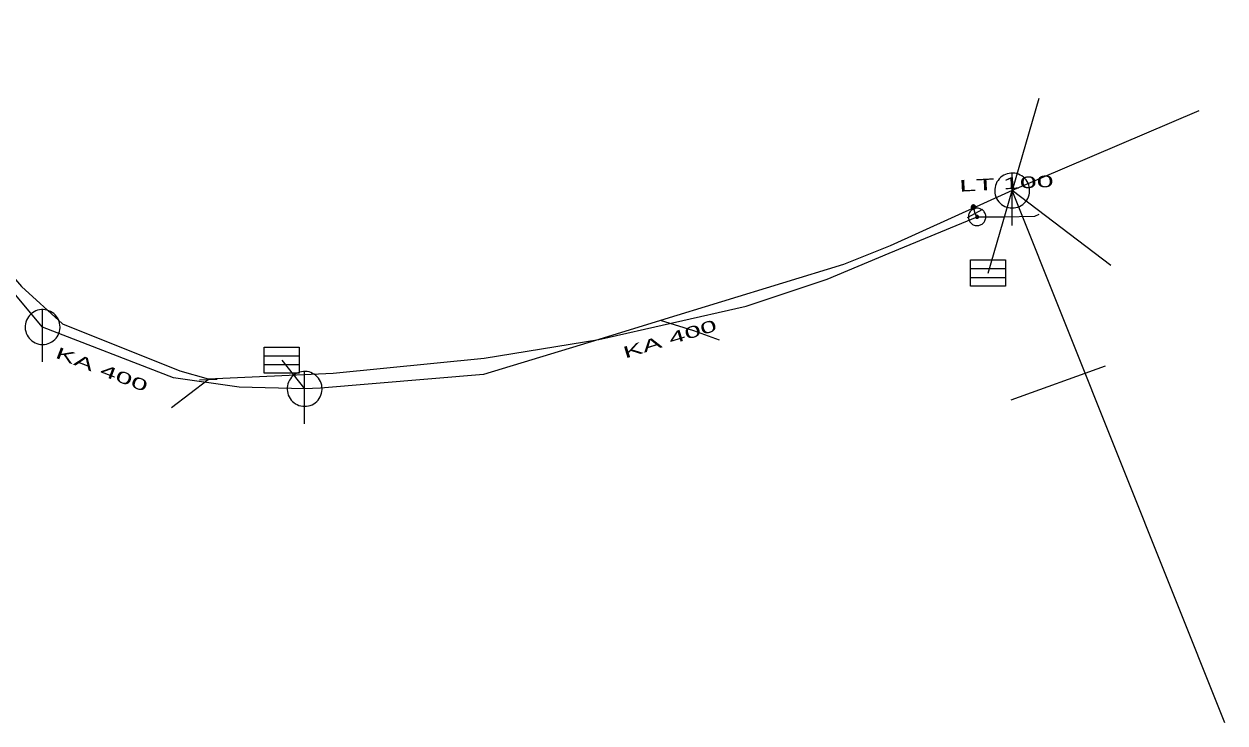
# Model space of a CAD drawing. Extents: x -688432 to -687974, y -973332 to -972704.
# Drawn here: x -688043 to -687974.2, y -972998.2 to -972958.2 of the extents above; entities that cross this region are included whole.
import ezdxf
from ezdxf.enums import TextEntityAlignment as Align

# ---------------------------------------------------------------- set-up
doc = ezdxf.new("R2010")
doc.units = 0
doc.header["$LTSCALE"] = 0.27
for name, color, linetype, lineweight in [('1', 7, 'Continuous', 25), ('11', 7, 'Continuous', 13), ('13', 7, 'Continuous', 13), ('14', 7, 'Continuous', 25), ('17', 7, 'Continuous', 25), ('22', 7, 'Continuous', 13), ('34', 7, 'Continuous', 13), ('47', 7, 'Continuous', 13), ('9', 7, 'Continuous', 13)]:
    doc.layers.add(name, color=color, linetype=linetype, lineweight=lineweight)

msp = doc.modelspace()

# ---------------------------------------------------------------- linework, layer by layer
at = {"layer": '11'}
for p, q in [((-687984.829, -972962.445), (-687986.359, -972967.719)), ((-687987.73, -972972.449), (-687986.359, -972967.719)), ((-687980.71, -972972.02), (-687986.359, -972967.719)), ((-688028.199, -972977.44), (-688026.89, -972979.079))]:
    msp.add_line(p, q, dxfattribs=at)
msp.add_lwpolyline([(-688003.12, -972976.289), (-688004.59, -972975.75), (-688006.5, -972975.16)], dxfattribs=at)
at = {"layer": '13'}
for p, q in [((-687981.03, -972977.77), (-687986.43, -972979.719)), ((-688032.407, -972978.563), (-688034.52, -972980.17))]:
    msp.add_line(p, q, dxfattribs=at)
at = {"layer": '14'}
for p in [(-687975.67, -972963.16), (-687974.17, -972998.219)]:
    msp.add_line(p, (-687986.359, -972967.719), dxfattribs=at)
at = {"layer": '14', "lineweight": 13}
for p, q in [((-687988.48, -972969.03), (-687988.579, -972968.67)), ((-687988.37, -972969.23), (-687988.48, -972969.03)), ((-688032.41, -972978.5), (-688032.407, -972978.563))]:
    msp.add_line(p, q, dxfattribs=at)
at = {"layer": '14'}
for points in [[(-688041.899, -972975.539), (-688045.67, -972971.059), (-688050.98, -972964.93), (-688055.91, -972959.239), (-688056.879, -972958.18)], [(-687986.359, -972967.719), (-687993.34, -972970.89), (-687996.03, -972971.96), (-688006.5, -972975.16), (-688010.039, -972976.26), (-688016.64, -972978.25), (-688025.98, -972979.039), (-688026.89, -972979.079)], [(-688026.89, -972979.079), (-688030.64, -972978.989), (-688034.41, -972978.44), (-688041.899, -972975.539)]]:
    msp.add_lwpolyline(points, dxfattribs=at)
at = {"layer": '17'}
for points in [[(-688050.016, -972965.189), (-688043.1, -972973.21), (-688040.76, -972975.36), (-688034.039, -972978.039), (-688032.41, -972978.5), (-688025.25, -972978.18), (-688016.6, -972977.329), (-688010.039, -972976.26), (-688001.6, -972974.35), (-687996.96, -972972.8), (-687993.41, -972971.309), (-687988.37, -972969.23)], [(-687988.37, -972969.23), (-687986.829, -972969.23), (-687985.07, -972969.188), (-687984.82, -972969.07)]]:
    msp.add_lwpolyline(points, dxfattribs=at)
at = {"layer": '22'}
for p, q in [((-687986.359, -972969.719), (-687986.358, -972966.719)), ((-687988.741, -972972.192), (-687986.741, -972972.192)), ((-687988.741, -972972.692), (-687986.741, -972972.692)), ((-688041.899, -972977.539), (-688041.898, -972974.539)), ((-688029.21, -972977.183), (-688027.21, -972977.183)), ((-688029.21, -972977.683), (-688027.21, -972977.683)), ((-688026.89, -972981.079), (-688026.889, -972978.079))]:
    msp.add_line(p, q, dxfattribs=at)
for points in [[(-687985.359, -972967.719), (-687985.364, -972967.61), (-687985.382, -972967.502), (-687985.412, -972967.396), (-687985.452, -972967.295), (-687985.504, -972967.198), (-687985.566, -972967.108), (-687985.638, -972967.025), (-687985.718, -972966.951), (-687985.806, -972966.885), (-687985.9, -972966.83), (-687986, -972966.785), (-687986.105, -972966.752), (-687986.212, -972966.73), (-687986.321, -972966.72), (-687986.431, -972966.722), (-687986.539, -972966.736), (-687986.646, -972966.761), (-687986.749, -972966.798), (-687986.847, -972966.847), (-687986.939, -972966.905), (-687987.025, -972966.974), (-687987.102, -972967.051), (-687987.171, -972967.137), (-687987.23, -972967.229), (-687987.278, -972967.327), (-687987.315, -972967.43), (-687987.341, -972967.537), (-687987.355, -972967.645), (-687987.358, -972967.755), (-687987.348, -972967.864), (-687987.327, -972967.971), (-687987.293, -972968.075), (-687987.249, -972968.175), (-687987.194, -972968.27), (-687987.128, -972968.358), (-687987.054, -972968.438), (-687986.971, -972968.51), (-687986.881, -972968.572), (-687986.785, -972968.624), (-687986.683, -972968.665), (-687986.578, -972968.695), (-687986.47, -972968.713), (-687986.36, -972968.719), (-687986.251, -972968.713), (-687986.143, -972968.695), (-687986.038, -972968.666), (-687985.936, -972968.625), (-687985.839, -972968.573), (-687985.749, -972968.511), (-687985.666, -972968.44), (-687985.591, -972968.36), (-687985.526, -972968.272), (-687985.47, -972968.178), (-687985.426, -972968.078), (-687985.392, -972967.974), (-687985.37, -972967.866), (-687985.36, -972967.757)], [(-687988.741, -972971.692), (-687986.741, -972971.692), (-687986.741, -972973.192), (-687988.741, -972973.192)], [(-688040.899, -972975.539), (-688040.904, -972975.43), (-688040.922, -972975.322), (-688040.952, -972975.216), (-688040.992, -972975.115), (-688041.044, -972975.018), (-688041.106, -972974.928), (-688041.178, -972974.845), (-688041.258, -972974.771), (-688041.346, -972974.705), (-688041.44, -972974.65), (-688041.54, -972974.605), (-688041.645, -972974.572), (-688041.752, -972974.55), (-688041.861, -972974.54), (-688041.971, -972974.542), (-688042.079, -972974.556), (-688042.186, -972974.581), (-688042.289, -972974.618), (-688042.387, -972974.667), (-688042.479, -972974.725), (-688042.565, -972974.794), (-688042.642, -972974.871), (-688042.711, -972974.957), (-688042.77, -972975.049), (-688042.818, -972975.147), (-688042.855, -972975.25), (-688042.881, -972975.357), (-688042.895, -972975.465), (-688042.898, -972975.575), (-688042.888, -972975.684), (-688042.867, -972975.791), (-688042.833, -972975.895), (-688042.789, -972975.995), (-688042.734, -972976.09), (-688042.668, -972976.178), (-688042.594, -972976.258), (-688042.511, -972976.33), (-688042.421, -972976.392), (-688042.325, -972976.444), (-688042.223, -972976.485), (-688042.118, -972976.515), (-688042.01, -972976.533), (-688041.9, -972976.539), (-688041.791, -972976.533), (-688041.683, -972976.515), (-688041.578, -972976.486), (-688041.476, -972976.445), (-688041.379, -972976.393), (-688041.289, -972976.331), (-688041.206, -972976.26), (-688041.131, -972976.18), (-688041.066, -972976.092), (-688041.01, -972975.998), (-688040.966, -972975.898), (-688040.932, -972975.794), (-688040.91, -972975.686), (-688040.9, -972975.577)], [(-688029.21, -972976.683), (-688027.21, -972976.683), (-688027.21, -972978.183), (-688029.21, -972978.183)], [(-688025.89, -972979.079), (-688025.895, -972978.97), (-688025.913, -972978.862), (-688025.943, -972978.756), (-688025.983, -972978.655), (-688026.035, -972978.558), (-688026.097, -972978.468), (-688026.169, -972978.385), (-688026.249, -972978.311), (-688026.337, -972978.245), (-688026.431, -972978.19), (-688026.531, -972978.145), (-688026.636, -972978.112), (-688026.743, -972978.09), (-688026.852, -972978.08), (-688026.962, -972978.082), (-688027.07, -972978.096), (-688027.177, -972978.121), (-688027.28, -972978.158), (-688027.378, -972978.207), (-688027.47, -972978.265), (-688027.556, -972978.334), (-688027.633, -972978.411), (-688027.702, -972978.497), (-688027.761, -972978.589), (-688027.809, -972978.687), (-688027.846, -972978.79), (-688027.872, -972978.897), (-688027.886, -972979.005), (-688027.889, -972979.115), (-688027.879, -972979.224), (-688027.858, -972979.331), (-688027.824, -972979.435), (-688027.78, -972979.535), (-688027.725, -972979.63), (-688027.659, -972979.718), (-688027.585, -972979.798), (-688027.502, -972979.87), (-688027.412, -972979.932), (-688027.316, -972979.984), (-688027.214, -972980.025), (-688027.109, -972980.055), (-688027.001, -972980.073), (-688026.891, -972980.079), (-688026.782, -972980.073), (-688026.674, -972980.055), (-688026.569, -972980.026), (-688026.467, -972979.985), (-688026.37, -972979.933), (-688026.28, -972979.871), (-688026.197, -972979.8), (-688026.122, -972979.72), (-688026.057, -972979.632), (-688026.001, -972979.538), (-688025.957, -972979.438), (-688025.923, -972979.334), (-688025.901, -972979.226), (-688025.891, -972979.117)]]:
    msp.add_lwpolyline(points, close=True, dxfattribs=at)
at = {"layer": '34'}
for p, q in [((-687988.917, -972969.271), (-687988.041, -972968.789)), ((-688031.907, -972978.54), (-688032.906, -972978.584))]:
    msp.add_line(p, q, dxfattribs=at)
at = {"layer": '47'}
for points in [[(-687987.907, -972969.039), (-687987.93, -972968.992), (-687987.957, -972968.947), (-687987.989, -972968.906), (-687988.025, -972968.868), (-687988.065, -972968.833), (-687988.108, -972968.804), (-687988.154, -972968.779), (-687988.202, -972968.759), (-687988.252, -972968.744), (-687988.304, -972968.734), (-687988.356, -972968.73), (-687988.408, -972968.732), (-687988.46, -972968.738), (-687988.511, -972968.75), (-687988.56, -972968.767), (-687988.607, -972968.79), (-687988.652, -972968.817), (-687988.694, -972968.85), (-687988.731, -972968.885), (-687988.766, -972968.925), (-687988.795, -972968.968), (-687988.821, -972969.014), (-687988.841, -972969.063), (-687988.856, -972969.112), (-687988.865, -972969.164), (-687988.869, -972969.216), (-687988.868, -972969.269), (-687988.861, -972969.32), (-687988.849, -972969.371), (-687988.832, -972969.42), (-687988.809, -972969.467), (-687988.782, -972969.512), (-687988.75, -972969.554), (-687988.714, -972969.591), (-687988.674, -972969.626), (-687988.632, -972969.656), (-687988.586, -972969.681), (-687988.537, -972969.701), (-687988.487, -972969.716), (-687988.435, -972969.725), (-687988.383, -972969.729), (-687988.331, -972969.729), (-687988.279, -972969.721), (-687988.228, -972969.709), (-687988.179, -972969.692), (-687988.132, -972969.669), (-687988.087, -972969.642), (-687988.046, -972969.611), (-687988.008, -972969.574), (-687987.973, -972969.534), (-687987.943, -972969.492), (-687987.919, -972969.446), (-687987.899, -972969.398), (-687987.884, -972969.347), (-687987.874, -972969.295), (-687987.87, -972969.243), (-687987.871, -972969.192), (-687987.878, -972969.139), (-687987.89, -972969.088)], [(-687988.294, -972969.198), (-687988.297, -972969.19), (-687988.302, -972969.183), (-687988.307, -972969.177), (-687988.313, -972969.17), (-687988.32, -972969.165), (-687988.327, -972969.16), (-687988.334, -972969.155), (-687988.342, -972969.152), (-687988.35, -972969.15), (-687988.359, -972969.148), (-687988.368, -972969.148), (-687988.376, -972969.148), (-687988.384, -972969.149), (-687988.392, -972969.15), (-687988.401, -972969.154), (-687988.409, -972969.157), (-687988.416, -972969.162), (-687988.422, -972969.167), (-687988.429, -972969.173), (-687988.434, -972969.18), (-687988.439, -972969.187), (-687988.444, -972969.194), (-687988.447, -972969.202), (-687988.45, -972969.211), (-687988.451, -972969.219), (-687988.451, -972969.228), (-687988.451, -972969.236), (-687988.45, -972969.244), (-687988.449, -972969.252), (-687988.445, -972969.261), (-687988.442, -972969.269), (-687988.437, -972969.276), (-687988.432, -972969.282), (-687988.426, -972969.289), (-687988.419, -972969.294), (-687988.413, -972969.299), (-687988.405, -972969.304), (-687988.397, -972969.307), (-687988.388, -972969.31), (-687988.38, -972969.311), (-687988.371, -972969.311), (-687988.363, -972969.311), (-687988.355, -972969.31), (-687988.347, -972969.309), (-687988.338, -972969.305), (-687988.33, -972969.302), (-687988.323, -972969.297), (-687988.317, -972969.292), (-687988.31, -972969.286), (-687988.305, -972969.279), (-687988.3, -972969.273), (-687988.295, -972969.265), (-687988.292, -972969.257), (-687988.29, -972969.249), (-687988.288, -972969.24), (-687988.288, -972969.231), (-687988.288, -972969.223), (-687988.289, -972969.215), (-687988.29, -972969.207)]]:
    msp.add_lwpolyline(points, close=True, dxfattribs=at)
at = {"layer": '9'}
for points in [[(-687988.705, -972968.67), (-687988.705, -972968.683), (-687988.703, -972968.696), (-687988.7, -972968.709), (-687988.695, -972968.721), (-687988.689, -972968.733), (-687988.682, -972968.744), (-687988.674, -972968.754), (-687988.664, -972968.764), (-687988.654, -972968.772), (-687988.643, -972968.779), (-687988.631, -972968.785), (-687988.619, -972968.79), (-687988.606, -972968.793), (-687988.593, -972968.795), (-687988.58, -972968.797), (-687988.567, -972968.796), (-687988.554, -972968.794), (-687988.541, -972968.791), (-687988.529, -972968.786), (-687988.517, -972968.78), (-687988.506, -972968.773), (-687988.496, -972968.765), (-687988.486, -972968.755), (-687988.478, -972968.745), (-687988.471, -972968.734), (-687988.465, -972968.722), (-687988.46, -972968.71), (-687988.457, -972968.697), (-687988.455, -972968.684), (-687988.453, -972968.671), (-687988.454, -972968.658), (-687988.456, -972968.645), (-687988.459, -972968.632), (-687988.464, -972968.62), (-687988.47, -972968.608), (-687988.477, -972968.597), (-687988.485, -972968.587), (-687988.495, -972968.577), (-687988.505, -972968.569), (-687988.516, -972968.562), (-687988.528, -972968.556), (-687988.54, -972968.551), (-687988.553, -972968.548), (-687988.566, -972968.546), (-687988.579, -972968.545), (-687988.592, -972968.545), (-687988.605, -972968.547), (-687988.618, -972968.55), (-687988.63, -972968.555), (-687988.642, -972968.561), (-687988.653, -972968.568), (-687988.663, -972968.576), (-687988.673, -972968.586), (-687988.681, -972968.596), (-687988.688, -972968.607), (-687988.694, -972968.619), (-687988.699, -972968.631), (-687988.702, -972968.644), (-687988.704, -972968.657)], [(-687988.685, -972968.67), (-687988.686, -972968.681), (-687988.684, -972968.692), (-687988.681, -972968.703), (-687988.677, -972968.713), (-687988.672, -972968.723), (-687988.666, -972968.732), (-687988.659, -972968.741), (-687988.651, -972968.749), (-687988.642, -972968.756), (-687988.633, -972968.762), (-687988.623, -972968.767), (-687988.613, -972968.771), (-687988.602, -972968.774), (-687988.591, -972968.777), (-687988.58, -972968.777), (-687988.569, -972968.777), (-687988.558, -972968.775), (-687988.547, -972968.772), (-687988.537, -972968.768), (-687988.527, -972968.763), (-687988.518, -972968.757), (-687988.509, -972968.75), (-687988.501, -972968.742), (-687988.494, -972968.733), (-687988.488, -972968.724), (-687988.483, -972968.714), (-687988.479, -972968.704), (-687988.476, -972968.693), (-687988.474, -972968.682), (-687988.473, -972968.671), (-687988.473, -972968.66), (-687988.475, -972968.649), (-687988.478, -972968.638), (-687988.482, -972968.628), (-687988.487, -972968.618), (-687988.493, -972968.609), (-687988.5, -972968.6), (-687988.508, -972968.592), (-687988.517, -972968.585), (-687988.526, -972968.579), (-687988.536, -972968.574), (-687988.546, -972968.57), (-687988.557, -972968.567), (-687988.568, -972968.565), (-687988.579, -972968.565), (-687988.59, -972968.564), (-687988.601, -972968.566), (-687988.612, -972968.569), (-687988.622, -972968.573), (-687988.632, -972968.578), (-687988.641, -972968.584), (-687988.65, -972968.591), (-687988.658, -972968.599), (-687988.665, -972968.608), (-687988.671, -972968.617), (-687988.676, -972968.627), (-687988.68, -972968.637), (-687988.683, -972968.648), (-687988.685, -972968.659)], [(-687988.666, -972968.67), (-687988.666, -972968.679), (-687988.665, -972968.688), (-687988.662, -972968.697), (-687988.659, -972968.705), (-687988.655, -972968.713), (-687988.65, -972968.721), (-687988.644, -972968.728), (-687988.638, -972968.734), (-687988.631, -972968.74), (-687988.623, -972968.745), (-687988.615, -972968.749), (-687988.607, -972968.752), (-687988.598, -972968.755), (-687988.589, -972968.756), (-687988.58, -972968.758), (-687988.571, -972968.757), (-687988.562, -972968.756), (-687988.553, -972968.753), (-687988.545, -972968.75), (-687988.537, -972968.746), (-687988.529, -972968.741), (-687988.522, -972968.735), (-687988.516, -972968.729), (-687988.51, -972968.722), (-687988.505, -972968.714), (-687988.501, -972968.706), (-687988.498, -972968.698), (-687988.495, -972968.689), (-687988.494, -972968.68), (-687988.492, -972968.671), (-687988.493, -972968.662), (-687988.494, -972968.653), (-687988.497, -972968.644), (-687988.5, -972968.636), (-687988.504, -972968.628), (-687988.509, -972968.62), (-687988.515, -972968.613), (-687988.521, -972968.607), (-687988.528, -972968.601), (-687988.536, -972968.596), (-687988.544, -972968.592), (-687988.552, -972968.589), (-687988.561, -972968.586), (-687988.57, -972968.585), (-687988.579, -972968.584), (-687988.588, -972968.584), (-687988.597, -972968.585), (-687988.606, -972968.588), (-687988.614, -972968.591), (-687988.622, -972968.595), (-687988.63, -972968.6), (-687988.637, -972968.606), (-687988.643, -972968.612), (-687988.649, -972968.619), (-687988.654, -972968.627), (-687988.658, -972968.635), (-687988.661, -972968.643), (-687988.664, -972968.652), (-687988.665, -972968.661)], [(-687988.646, -972968.67), (-687988.646, -972968.677), (-687988.645, -972968.684), (-687988.644, -972968.691), (-687988.641, -972968.697), (-687988.638, -972968.703), (-687988.634, -972968.709), (-687988.63, -972968.715), (-687988.625, -972968.72), (-687988.619, -972968.724), (-687988.613, -972968.728), (-687988.607, -972968.731), (-687988.601, -972968.734), (-687988.594, -972968.735), (-687988.587, -972968.738), (-687988.58, -972968.738), (-687988.573, -972968.738), (-687988.566, -972968.736), (-687988.559, -972968.735), (-687988.553, -972968.732), (-687988.546, -972968.729), (-687988.541, -972968.725), (-687988.535, -972968.721), (-687988.53, -972968.716), (-687988.526, -972968.71), (-687988.522, -972968.704), (-687988.519, -972968.698), (-687988.516, -972968.692), (-687988.514, -972968.685), (-687988.513, -972968.678), (-687988.512, -972968.671), (-687988.512, -972968.664), (-687988.513, -972968.657), (-687988.515, -972968.65), (-687988.518, -972968.644), (-687988.521, -972968.637), (-687988.525, -972968.632), (-687988.529, -972968.626), (-687988.534, -972968.621), (-687988.54, -972968.617), (-687988.545, -972968.613), (-687988.552, -972968.61), (-687988.558, -972968.607), (-687988.565, -972968.605), (-687988.572, -972968.604), (-687988.579, -972968.604), (-687988.586, -972968.604), (-687988.593, -972968.604), (-687988.6, -972968.606), (-687988.606, -972968.609), (-687988.612, -972968.612), (-687988.618, -972968.616), (-687988.624, -972968.62), (-687988.629, -972968.625), (-687988.633, -972968.631), (-687988.637, -972968.636), (-687988.64, -972968.643), (-687988.643, -972968.649), (-687988.644, -972968.656), (-687988.646, -972968.663)], [(-687988.626, -972968.67), (-687988.626, -972968.675), (-687988.626, -972968.68), (-687988.625, -972968.685), (-687988.623, -972968.689), (-687988.621, -972968.694), (-687988.618, -972968.698), (-687988.615, -972968.701), (-687988.611, -972968.705), (-687988.608, -972968.708), (-687988.604, -972968.711), (-687988.599, -972968.713), (-687988.595, -972968.715), (-687988.59, -972968.716), (-687988.585, -972968.718), (-687988.58, -972968.718), (-687988.575, -972968.718), (-687988.57, -972968.717), (-687988.565, -972968.716), (-687988.561, -972968.714), (-687988.556, -972968.712), (-687988.552, -972968.709), (-687988.548, -972968.706), (-687988.545, -972968.702), (-687988.542, -972968.699), (-687988.539, -972968.695), (-687988.537, -972968.69), (-687988.535, -972968.686), (-687988.534, -972968.681), (-687988.533, -972968.676), (-687988.532, -972968.671), (-687988.532, -972968.666), (-687988.533, -972968.661), (-687988.534, -972968.656), (-687988.536, -972968.652), (-687988.538, -972968.647), (-687988.541, -972968.643), (-687988.544, -972968.639), (-687988.547, -972968.636), (-687988.551, -972968.633), (-687988.555, -972968.63), (-687988.56, -972968.628), (-687988.564, -972968.626), (-687988.569, -972968.625), (-687988.574, -972968.624), (-687988.579, -972968.624), (-687988.584, -972968.624), (-687988.589, -972968.625), (-687988.594, -972968.625), (-687988.598, -972968.627), (-687988.603, -972968.629), (-687988.607, -972968.632), (-687988.61, -972968.635), (-687988.614, -972968.638), (-687988.617, -972968.642), (-687988.62, -972968.646), (-687988.622, -972968.651), (-687988.624, -972968.655), (-687988.625, -972968.66), (-687988.626, -972968.665)], [(-687988.606, -972968.67), (-687988.606, -972968.673), (-687988.607, -972968.676), (-687988.606, -972968.678), (-687988.605, -972968.681), (-687988.604, -972968.684), (-687988.602, -972968.686), (-687988.6, -972968.688), (-687988.598, -972968.69), (-687988.596, -972968.692), (-687988.594, -972968.694), (-687988.591, -972968.696), (-687988.588, -972968.697), (-687988.586, -972968.697), (-687988.583, -972968.698), (-687988.58, -972968.698), (-687988.577, -972968.698), (-687988.574, -972968.698), (-687988.571, -972968.697), (-687988.569, -972968.696), (-687988.566, -972968.695), (-687988.564, -972968.693), (-687988.561, -972968.691), (-687988.559, -972968.689), (-687988.558, -972968.687), (-687988.556, -972968.685), (-687988.555, -972968.682), (-687988.553, -972968.679), (-687988.553, -972968.677), (-687988.552, -972968.674), (-687988.551, -972968.671), (-687988.552, -972968.668), (-687988.552, -972968.665), (-687988.553, -972968.662), (-687988.554, -972968.66), (-687988.555, -972968.657), (-687988.557, -972968.655), (-687988.558, -972968.652), (-687988.56, -972968.65), (-687988.563, -972968.649), (-687988.565, -972968.647), (-687988.568, -972968.646), (-687988.57, -972968.645), (-687988.573, -972968.644), (-687988.576, -972968.644), (-687988.579, -972968.643), (-687988.582, -972968.644), (-687988.585, -972968.643), (-687988.587, -972968.645), (-687988.59, -972968.645), (-687988.593, -972968.646), (-687988.595, -972968.648), (-687988.597, -972968.649), (-687988.599, -972968.651), (-687988.601, -972968.654), (-687988.603, -972968.656), (-687988.604, -972968.659), (-687988.605, -972968.661), (-687988.606, -972968.664), (-687988.606, -972968.667)], [(-687988.587, -972968.67), (-687988.587, -972968.672), (-687988.587, -972968.672), (-687988.586, -972968.672), (-687988.586, -972968.674), (-687988.587, -972968.675), (-687988.585, -972968.675), (-687988.585, -972968.675), (-687988.585, -972968.677), (-687988.585, -972968.677), (-687988.584, -972968.678), (-687988.582, -972968.678), (-687988.582, -972968.678), (-687988.582, -972968.679), (-687988.58, -972968.679), (-687988.58, -972968.679), (-687988.579, -972968.679), (-687988.578, -972968.679), (-687988.578, -972968.678), (-687988.577, -972968.678), (-687988.575, -972968.678), (-687988.575, -972968.677), (-687988.575, -972968.677), (-687988.574, -972968.676), (-687988.574, -972968.676), (-687988.572, -972968.675), (-687988.572, -972968.674), (-687988.571, -972968.673), (-687988.571, -972968.673), (-687988.571, -972968.672), (-687988.571, -972968.671), (-687988.571, -972968.67), (-687988.571, -972968.669), (-687988.571, -972968.669), (-687988.572, -972968.668), (-687988.572, -972968.667), (-687988.573, -972968.666), (-687988.573, -972968.666), (-687988.574, -972968.665), (-687988.574, -972968.665), (-687988.575, -972968.664), (-687988.576, -972968.664), (-687988.577, -972968.663), (-687988.577, -972968.663), (-687988.578, -972968.663), (-687988.579, -972968.663), (-687988.58, -972968.663), (-687988.581, -972968.663), (-687988.581, -972968.663), (-687988.582, -972968.664), (-687988.583, -972968.663), (-687988.584, -972968.665), (-687988.584, -972968.665), (-687988.585, -972968.665), (-687988.585, -972968.665), (-687988.586, -972968.667), (-687988.586, -972968.668), (-687988.586, -972968.669), (-687988.587, -972968.669), (-687988.587, -972968.67)]]:
    msp.add_lwpolyline(points, close=True, dxfattribs=at)

# ---------------------------------------------------------------- texts
at = {"layer": '1'}
for s, rotation, width, p in [('LT 100', 3, 1.95, (-687986.6754, -972967.6452)), ('LT 100', 3, 1.95, (-687986.6754, -972967.6452)), ('LT 100', 3, 1.95, (-687986.6754, -972967.6452)), ('LT 100', 3, 1.95, (-687986.6754, -972967.6452)), ('LT 100', 3, 1.95, (-687986.6754, -972967.6452)), ('KA 400', 17, 1.9, (-688005.8715, -972976.5345)), ('KA 400', 17, 1.9, (-688005.8715, -972976.5345)), ('KA 400', 17, 1.9, (-688005.8715, -972976.5345)), ('KA 400', 17, 1.9, (-688005.8715, -972976.5345)), ('KA 400', 17, 1.9, (-688005.8715, -972976.5345)), ('KA 400', 339, 1.9, (-688038.6255, -972978.2747)), ('KA 400', 339, 1.9, (-688038.6255, -972978.2747)), ('KA 400', 339, 1.9, (-688038.6255, -972978.2747)), ('KA 400', 339, 1.9, (-688038.6255, -972978.2747)), ('KA 400', 339, 1.9, (-688038.6255, -972978.2747))]:
    msp.add_text(s, height=0.6667, rotation=rotation, dxfattribs=dict(at, width=width)).set_placement(p, align=Align.CENTER)

doc.saveas('drawing.dxf')
